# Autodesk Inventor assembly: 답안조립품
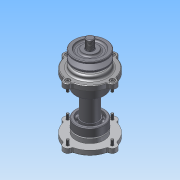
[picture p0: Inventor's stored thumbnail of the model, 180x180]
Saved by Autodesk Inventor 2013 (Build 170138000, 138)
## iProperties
Created: 2015-12
Part Number: 답안조립품
Document SubType Name: Assembly
Designer: user-11
Author: user-11
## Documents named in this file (10)
- C:\Users\user-11\Desktop\451207V1008\답안조립품.iam
- C:\Users\user-11\Desktop\451207V1008\1-본체.ipt
- C:\Users\user-11\Desktop\451207V1008\커버.ipt
- C:\Users\user-11\Desktop\451207V1008\커버2.ipt
- C:\Users\user-11\Desktop\451207V1008\볼트 M4 x 12.ipt
- C:\Users\user-11\Desktop\451207V1008\베어링 6204.ipt
- C:\Users\user-11\Desktop\451207V1008\축.ipt
- C:\Users\user-11\Desktop\451207V1008\키(4 x 4 x 12).ipt
- C:\Users\user-11\Desktop\451207V1008\V-벨트풀리.ipt
- C:\Users\user-11\Desktop\451207V1008\오일실.ipt
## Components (6 placed, 5 different names)
1. 1-본체:1
2. KS B 2023 6204 - 20 x 47 x 14:1
3. KS B 2023 6204 - 20 x 47 x 14:2
4. KS B 1311 (I) 4 x 4 x 12:1 — 각도:1, 각도:2
5. V-벨트풀리:1 — 각도:2
6. KS B 2804 D D - 20 32 8:1
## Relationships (2: Angle 2)
- 각도:1 [Angle]: KS B 1311 (I) 4 x 4 x 12:1
- 각도:2 [Angle]: KS B 1311 (I) 4 x 4 x 12:1 ↔ V-벨트풀리:1
